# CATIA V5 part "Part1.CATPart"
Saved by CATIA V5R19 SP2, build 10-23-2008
Part number: Part1
Bounding box of the stored display mesh (mm): x -1250 to 1750, y -750 to 750, z 0 to 0
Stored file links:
  C:\BEHROOZ\catia learning\tarh haye mashin\hb\Part1.CATPart
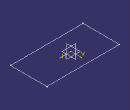
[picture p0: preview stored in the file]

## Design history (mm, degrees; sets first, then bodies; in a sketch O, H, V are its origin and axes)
Body1 (main body)
  Sketch1 on xy-plane, origin (0, 0, 0), H (1, 0, 0), V (0, 1, 0)
    line L1 (1750, 750) -> (1750, -750)
    line L2 (1750, -750) -> (-1250, -750)
    line L3 (-1250, -750) -> (-1250, 750)
    line L4 (-1250, 750) -> (1750, 750)
    distance L2 L4 = 1500
    distance L1 L3 = 3000
  Sketch2 on zx-plane, origin (0, 0, 0), H (-1, 0, 0), V (0, 0, 1)
    line L1 (1187.0274, 782.9605) -> (1097.9585, 712.4737)
    line L2 (1097.9585, 712.4737) -> (1152.1112, 565.6462)
    line L3 (1211.7794, 142.1118) -> (1074.8606, 0)
    line L4 (-1821.2993, 0) -> (1250, 0)
    line L5 (1187.0274, 782.9605) -> (505.4854, 951.1716)
    arc A1 centre (-406.8856, -9065.1907) radius 10057.8295 from (505.4854, 951.1716) to (-685.3901, 988.7822) ccw
    arc A2 centre (271.7166, -1257.5936) radius 2441.7734 from (-1217.5713, 677.4203) to (-685.3901, 988.7822) cw
    line L6 (457.1478, 904.1931) -> (645.989, 812.8011)
    line L7 (645.989, 812.8011) -> (543.0323, 785.2419)
    line L8 (-1029.2606, 587.2901) -> (-1172.3187, 668.0043)
    arc A3 centre (370.5705, -1314.7197) radius 2512.31 from (-1172.3187, 668.0043) to (-683.133, 965.9404) cw
    arc A4 centre (-466.0099, -5584.0666) radius 6553.6046 from (-683.133, 965.9404) to (457.1478, 904.1931) cw
    circle A5 centre (845.606, 208.1688) radius 251.3368
    arc A6 centre (1589.552, -12678.1554) radius 13467.1328 from (1187.0274, 782.9605) to (-1376.9419, 458.1904) ccw
    arc A7 centre (1136.3128, -10270.2549) radius 11071.4042 from (543.0323, 785.2419) to (-1029.2606, 587.2901) ccw
    line L9 (353.7012, 97.7708) -> (493.1505, 322.1249)
    arc A8 centre (-831.0348, -15069.2644) radius 15448.2469 from (493.1505, 322.1249) to (-1213.9619, 374.2358) ccw
    arc A9 centre (-423.9888, -1807.092) radius 2608.1746 from (-1791.5363, 413.8061) to (-1217.5713, 677.4203) cw
    circle A10 centre (-1402.6201, 208.1688) radius 251.3368
    arc A11 centre (-700.7544, 373.3765) radius 1181.1143 from (-1821.2993, 0) to (-1878.1877, 280.2012) cw
    line L10 (-1854.3133, 339.6581) -> (-1791.5363, 413.8061)
    arc A12 centre (-2835.5431, 52064.8447) radius 52064.8447 from (353.7012, 97.7708) to (-1230.798, 24.7366) cw
    line L11 (-1564.0505, 15.5281) -> (-1824.3133, 9.1702)
    line L12 (-1376.9419, 458.1904) -> (-1854.3133, 339.6581)
    arc A13 centre (-1142.0294, -2526.8107) radius 2901.9382 from (-1213.9619, 374.2358) to (-1878.1877, 280.2012) ccw
    line L13 (-1849.6886, 340.8064) -> (-1869.2877, 282.5202)
    arc A14 centre (2056.9818, -8891.0735) radius 9651.3131 from (1097.9585, 712.4737) to (271.7166, 593.6865) ccw
    line L14 (271.7166, 593.6865) -> (415.4664, 504.3375)
    arc A15 centre (1232.4419, -4927.5862) radius 5493.0178 from (415.4664, 504.3375) to (1171.9788, 565.0988) cw
    arc A16 centre (715.1145, 308.7446) radius 523.8726 from (1171.9788, 565.0988) to (1211.7794, 142.1118) cw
